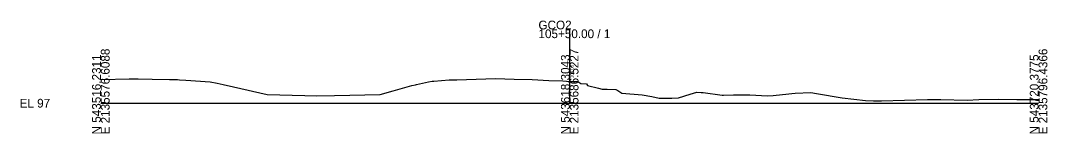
# Model space of a CAD drawing. Extents: x -14327 to 8886, y -10 to 39048.
# Drawn here: x 3974.3 to 4302.8, y 30990.3 to 31026.5 of the extents above; entities that cross this region are included whole.
import ezdxf

# ---------------------------------------------------------------- set-up
doc = ezdxf.new("R2010")
doc.units = 0
for name, color, linetype in [('RD_GPK_XS_Cell', 7, 'Continuous'), ('RD_XS_ExGround', 7, 'Continuous'), ('RD_XS_TX_Elev_EX', 7, 'Continuous')]:
    doc.layers.add(name, color=color, linetype=linetype)

msp = doc.modelspace()

# ---------------------------------------------------------------- linework, layer by layer
at = {"layer": 'RD_GPK_XS_Cell'}
for p, q in [((4150, 31000), (4150, 31023.64)), ((4000, 31000), (4150, 31000)), ((4150, 31000), (4300, 31000))]:
    msp.add_line(p, q, dxfattribs=at)
at = {"layer": 'RD_XS_ExGround'}
for p, q in [((4000, 31007.59), (4000.21, 31007.6)), ((4000.21, 31007.6), (4009.09, 31007.78)), ((4009.09, 31007.78), (4011.92, 31007.84)), ((4011.92, 31007.84), (4016.41, 31007.73)), ((4016.41, 31007.73), (4021.97, 31007.61)), ((4021.97, 31007.61), (4024.51, 31007.54)), ((4024.51, 31007.54), (4025.17, 31007.51)), ((4025.17, 31007.51), (4027.24, 31007.43)), ((4027.24, 31007.43), (4034.99, 31006.89)), ((4104.83, 31006.8), (4105.96, 31007.04)), ((4105.96, 31007.04), (4106.48, 31007.07)), ((4106.48, 31007.07), (4111.4, 31007.45)), ((4111.4, 31007.45), (4113.31, 31007.49)), ((4113.31, 31007.49), (4113.92, 31007.5)), ((4113.92, 31007.5), (4116.93, 31007.6)), ((4116.93, 31007.6), (4126.23, 31007.88)), ((4126.23, 31007.88), (4132.21, 31007.72)), ((4132.21, 31007.72), (4138.03, 31007.54)), ((4138.03, 31007.54), (4143.36, 31007.31)), ((4143.36, 31007.31), (4147.83, 31007.15)), ((4147.83, 31007.15), (4150.16, 31006.99)), ((4150.16, 31006.99), (4151.12, 31006.92)), ((4151.12, 31006.92), (4152.6, 31006.95)), ((4152.6, 31006.95), (4153.58, 31006.27)), ((4034.99, 31006.89), (4037.26, 31006.39)), ((4037.26, 31006.39), (4039.12, 31005.99)), ((4039.12, 31005.99), (4042.42, 31005.24)), ((4042.42, 31005.24), (4053.16, 31002.83)), ((4089.39, 31002.78), (4093.57, 31003.98)), ((4093.57, 31003.98), (4099.52, 31005.65)), ((4099.52, 31005.65), (4100.61, 31005.9)), ((4100.61, 31005.9), (4100.99, 31006.03)), ((4100.99, 31006.03), (4104.83, 31006.8)), ((4153.58, 31006.27), (4155.35, 31006.19)), ((4155.35, 31006.19), (4155.67, 31005.72)), ((4155.67, 31005.72), (4159.22, 31004.8)), ((4159.22, 31004.8), (4160.34, 31004.51)), ((4160.34, 31004.51), (4162.02, 31004.45)), ((4162.02, 31004.45), (4164.75, 31004.42)), ((4164.75, 31004.42), (4165.39, 31004.03)), ((4165.39, 31004.03), (4166.72, 31003.25)), ((4053.16, 31002.83), (4065.22, 31002.51)), ((4065.22, 31002.51), (4068.96, 31002.34)), ((4068.96, 31002.34), (4074.76, 31002.52)), ((4074.76, 31002.52), (4089.39, 31002.78)), ((4166.72, 31003.25), (4173.17, 31002.69)), ((4173.17, 31002.69), (4176.32, 31002.15)), ((4176.32, 31002.15), (4178.59, 31001.61)), ((4178.59, 31001.61), (4182.63, 31001.64)), ((4182.63, 31001.64), (4184.76, 31001.74)), ((4184.76, 31001.74), (4188.57, 31002.93)), ((4188.57, 31002.93), (4190.64, 31003.56)), ((4190.64, 31003.56), (4192.07, 31003.46)), ((4192.07, 31003.46), (4192.68, 31003.46)), ((4192.68, 31003.46), (4198.82, 31002.61)), ((4198.82, 31002.61), (4199.23, 31002.61)), ((4199.23, 31002.61), (4202.37, 31002.64)), ((4202.37, 31002.64), (4202.91, 31002.65)), ((4202.91, 31002.65), (4203.32, 31002.66)), ((4203.32, 31002.66), (4205.96, 31002.68)), ((4205.96, 31002.68), (4207.15, 31002.68)), ((4207.15, 31002.68), (4207.57, 31002.66)), ((4207.57, 31002.66), (4213.31, 31002.33)), ((4213.31, 31002.33), (4215.06, 31002.43)), ((4215.06, 31002.43), (4220.13, 31003.05)), ((4220.13, 31003.05), (4221.03, 31003.12)), ((4221.03, 31003.12), (4222.17, 31003.22)), ((4222.17, 31003.22), (4227.16, 31003.38)), ((4227.16, 31003.38), (4228.95, 31003.06)), ((4228.95, 31003.06), (4237.17, 31001.71)), ((4237.17, 31001.71), (4244.67, 31000.88)), ((4244.67, 31000.88), (4247.18, 31000.76)), ((4247.18, 31000.76), (4249.77, 31000.76)), ((4249.77, 31000.76), (4264.43, 31001.22)), ((4264.43, 31001.22), (4267.19, 31001.18)), ((4267.19, 31001.18), (4268.7, 31001.16)), ((4268.7, 31001.16), (4277.2, 31001)), ((4277.2, 31001), (4280.88, 31001.16)), ((4280.88, 31001.16), (4287.2, 31001.28)), ((4287.2, 31001.28), (4293.05, 31001.17)), ((4293.05, 31001.17), (4300, 31001.16))]:
    msp.add_line(p, q, dxfattribs=at)

# ---------------------------------------------------------------- texts
at = {"layer": 'RD_GPK_XS_Cell'}
for s, p in [('GCO2', (4140, 31023.64)), ('105+50.00 / 1', (4140, 31020.84)), ('EL 97', (3974, 30998.6))]:
    msp.add_text(s, height=2.8, dxfattribs=at).set_placement(p)
for s, p in [('E 2135576.6088', (4002.8, 30990)), ('E 2135686.5227', (4152.8, 30990)), ('E 2135796.4366', (4302.8, 30990)), ('N 543516.2311', (4000, 30990)), ('N 543618.3043', (4150, 30990)), ('N 543720.3775', (4300, 30990))]:
    msp.add_text(s, height=2.8, rotation=90, dxfattribs=at).set_placement(p)
at = {"layer": 'RD_XS_TX_Elev_EX'}
msp.add_text('104.00', height=1, rotation=90, dxfattribs=at).set_placement((4151.25, 31008))

doc.saveas('drawing.dxf')
